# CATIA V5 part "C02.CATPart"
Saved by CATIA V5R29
Part number: C02
Bounding box of the stored display mesh (mm): x -32.98 to 32.98, y -100 to 300, z -33 to 33
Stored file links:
  C:\Users\제5강의실-23\Desktop\C02.CATPart
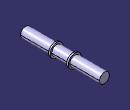
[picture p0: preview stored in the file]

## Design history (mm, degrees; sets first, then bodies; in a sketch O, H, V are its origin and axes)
Body1 (main body)
  DatumCurve1
  Sketch1 on zx-plane, origin (0, 0, 0), H (-1, 0, 0), V (0, 0, 1)
    circle A1 centre (0, 0) radius 25
    radius A1 = 25
  Pad1: profile Sketch1, direction (0, 1, 0), length 300, opposite side length 100
  Sketch2 on yz-plane, origin (0, 0, 0), H (0, 1, 0), V (0, 0, 1)
    line L1 (150, 33) -> (142, 33)
    line L2 (142, 33) -> (142, 25)
    line L3 (142, 25) -> (150, 25)
    line L4 (150, 25) -> (150, 33)
    point P5 (58, 33)
    line L5 (58, 33) -> (50, 33)
    line L6 (50, 33) -> (50, 25)
    line L7 (50, 25) -> (58, 25)
    line L8 (58, 25) -> (58, 33)
    point P7 (50, 25)
    reference intersected line E1 through (0, 0) direction (-1, 0) from xy-plane
    reference intersected line E2 through (0, 0) direction (0, 1) from zx-plane
    reference intersected line E3 (300, 25) -> (300, -25) from end face of Pad1
    length L1 = 8
    length L5 = 8
    length L2 = 8
    distance L3 E1 = 25
    distance L6 E2 = 50
    distance L6 L4 = 100 (reference)
    distance L4 E3 = 150
    horizontal: L1 H, L3 H, L5 H, L7 H
    vertical: L2 V, L4 V, L6 V, L8 V
    coincidence: P5 L1, P7 L3
  Shaft1: profile Sketch2, axis axis of face of Pad1 from Sketch1.A1, angle 360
